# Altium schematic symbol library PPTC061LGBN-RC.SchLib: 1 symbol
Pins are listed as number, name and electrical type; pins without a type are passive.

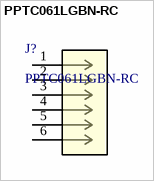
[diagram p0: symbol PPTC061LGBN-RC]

## PPTC061LGBN-RC
designator J?
No Description Available; Manufacturer_Name: Sullins
footprint CONN_PPTC061LGBN-RC_SUL
pins: 1, 2, 3, 4, 5, 6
